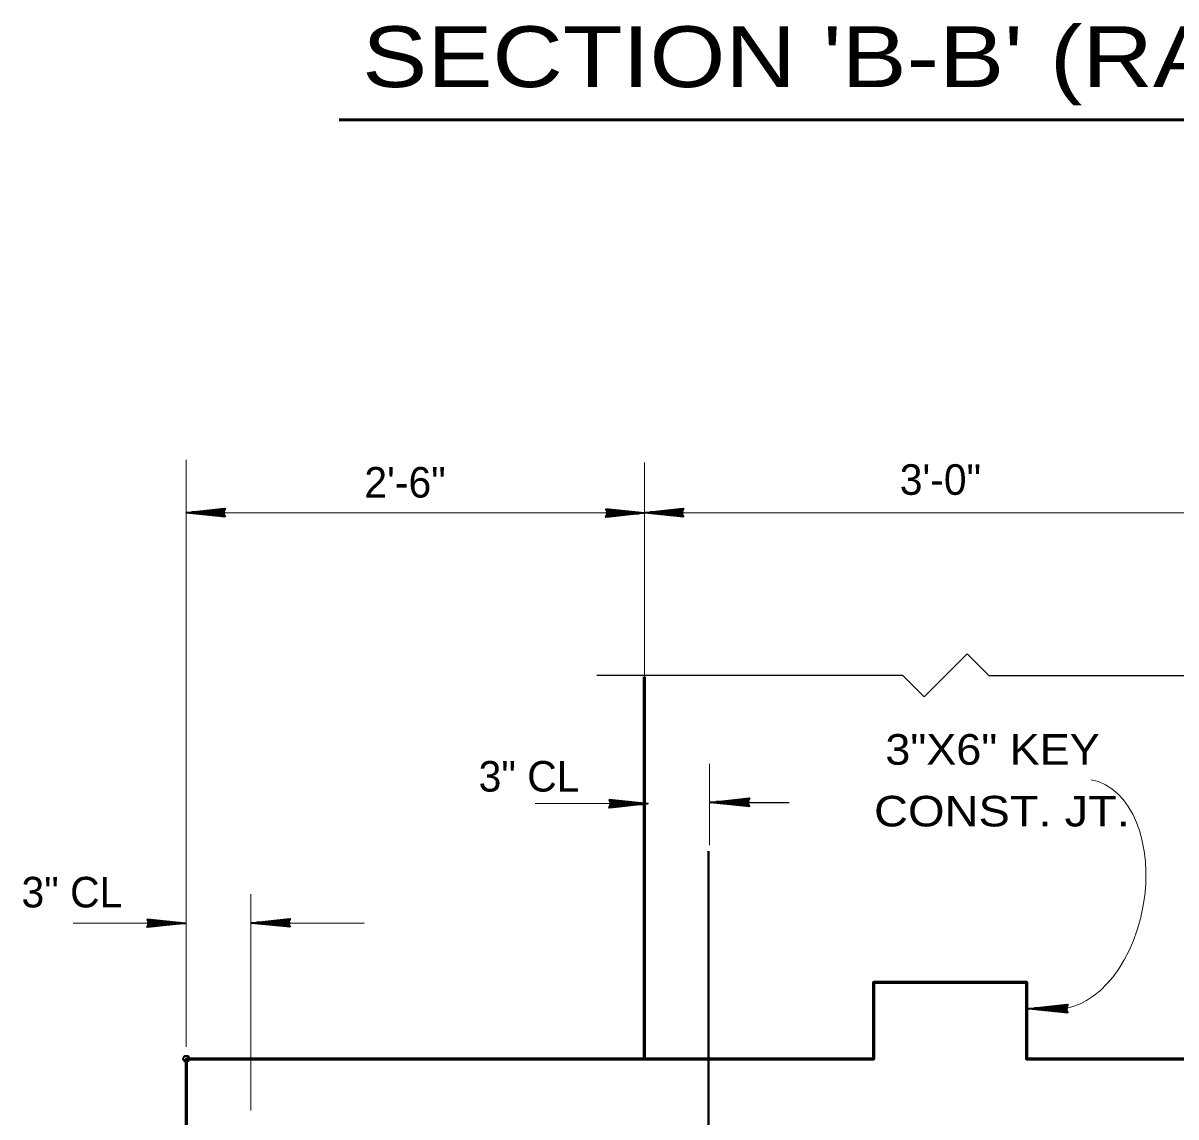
# Model space of a CAD drawing. Extents: x 4.49 to 7.69, y 0.28 to 2.27.
# Drawn here: x 5.7738 to 6.0882, y 1.4815 to 1.7797 of the extents above; entities that cross this region are included whole.
import ezdxf

# ---------------------------------------------------------------- set-up
doc = ezdxf.new("R2010")
doc.units = 0
doc.header["$LTSCALE"] = 0.0033
doc.header["$PDMODE"] = 32
doc.header["$PDSIZE"] = 0.00165
doc.layers.add('1', color=7, linetype='Continuous', lineweight=35)

msp = doc.modelspace()

# ---------------------------------------------------------------- linework, layer by layer
at = {"layer": '1', "lineweight": 53}
msp.add_line((5.86, 1.753333), (6.184583, 1.753333), dxfattribs=at)
at = {"layer": '1', "lineweight": 13}
for p, q in [((5.81825, 1.500583), (5.81825, 1.660667)), ((5.94325, 1.6015), (5.94325, 1.659917)), ((5.8185, 1.646167), (6.235167, 1.646167)), ((5.961, 1.555583), (5.961, 1.57775)), ((5.913417, 1.566917), (5.93425, 1.566917)), ((5.835917, 1.48325), (5.835917, 1.542167)), ((5.787417, 1.534333), (5.80825, 1.534333)), ((5.845917, 1.534333), (5.86675, 1.534333))]:
    msp.add_line(p, q, dxfattribs=at)
at = {"layer": '1'}
for p, q in [((5.828833, 1.646167), (5.81825, 1.646167)), ((5.828583, 1.645333), (5.82075, 1.646333)), ((5.828583, 1.645333), (5.82075, 1.646167)), ((5.828583, 1.645167), (5.82075, 1.646083)), ((5.828583, 1.645167), (5.82075, 1.646083)), ((5.828583, 1.64525), (5.82075, 1.646083)), ((5.828583, 1.64725), (5.82125, 1.646417)), ((5.828583, 1.647083), (5.82125, 1.646333)), ((5.828583, 1.647), (5.82125, 1.646167)), ((5.828667, 1.646833), (5.821333, 1.646083)), ((5.932667, 1.646167), (5.94325, 1.646167)), ((5.932833, 1.6455), (5.940167, 1.64625)), ((5.932917, 1.647167), (5.94075, 1.64625)), ((5.932917, 1.647167), (5.94075, 1.64625)), ((5.932917, 1.647083), (5.94075, 1.64625)), ((5.932917, 1.647), (5.94075, 1.646167)), ((5.932917, 1.647), (5.94075, 1.646)), ((5.932917, 1.645333), (5.94025, 1.646167)), ((5.932917, 1.64525), (5.94025, 1.646)), ((5.932917, 1.645083), (5.94025, 1.645917)), ((5.953833, 1.646167), (5.94325, 1.646167)), ((5.953583, 1.645333), (5.94575, 1.646333)), ((5.953583, 1.645333), (5.94575, 1.646167)), ((5.953583, 1.645167), (5.94575, 1.646083)), ((5.953583, 1.645167), (5.94575, 1.646083)), ((5.953583, 1.64525), (5.94575, 1.646083)), ((5.953583, 1.64725), (5.94625, 1.646417)), ((5.953583, 1.647083), (5.94625, 1.646333)), ((5.953583, 1.647), (5.94625, 1.646167)), ((5.953667, 1.646833), (5.946333, 1.646083)), ((5.933583, 1.566917), (5.944167, 1.566917)), ((5.93375, 1.56625), (5.941083, 1.567)), ((5.933833, 1.567917), (5.941667, 1.567)), ((5.933833, 1.567917), (5.941667, 1.567)), ((5.933833, 1.567833), (5.941667, 1.567)), ((5.933833, 1.56775), (5.941667, 1.566917)), ((5.933833, 1.56775), (5.941667, 1.56675)), ((5.933833, 1.566083), (5.941167, 1.566917)), ((5.933833, 1.566), (5.941167, 1.56675)), ((5.933833, 1.565833), (5.941167, 1.566667)), ((5.971833, 1.567167), (5.96125, 1.567167)), ((5.971583, 1.566333), (5.96375, 1.567333)), ((5.971583, 1.566333), (5.96375, 1.567167)), ((5.971583, 1.566167), (5.96375, 1.567083)), ((5.971583, 1.566167), (5.96375, 1.567083)), ((5.971583, 1.56625), (5.96375, 1.567083)), ((5.971583, 1.56825), (5.96425, 1.567417)), ((5.971583, 1.568083), (5.96425, 1.567333)), ((5.971583, 1.568), (5.96425, 1.567167)), ((5.971667, 1.567833), (5.964333, 1.567083)), ((5.807583, 1.534333), (5.818167, 1.534333)), ((5.80775, 1.533667), (5.815083, 1.534417)), ((5.807833, 1.535333), (5.815667, 1.534417)), ((5.807833, 1.535333), (5.815667, 1.534417)), ((5.807833, 1.53525), (5.815667, 1.534417)), ((5.807833, 1.535167), (5.815667, 1.534333)), ((5.807833, 1.535167), (5.815667, 1.534167)), ((5.807833, 1.5335), (5.815167, 1.534333)), ((5.846583, 1.534333), (5.836, 1.534333)), ((5.846333, 1.5335), (5.8385, 1.5345)), ((5.846333, 1.5335), (5.8385, 1.534333)), ((5.846333, 1.535417), (5.839, 1.534583)), ((5.846333, 1.53525), (5.839, 1.5345)), ((5.846333, 1.535167), (5.839, 1.534333)), ((5.846417, 1.535), (5.839083, 1.53425)), ((5.807833, 1.533417), (5.815167, 1.534167)), ((5.807833, 1.53325), (5.815167, 1.534083)), ((5.846333, 1.533333), (5.8385, 1.53425)), ((5.846333, 1.533333), (5.8385, 1.53425)), ((5.846333, 1.533417), (5.8385, 1.53425)), ((6.058667, 1.510917), (6.048083, 1.510917)), ((6.058417, 1.510083), (6.050583, 1.511083)), ((6.058417, 1.510083), (6.050583, 1.510917)), ((6.058417, 1.509917), (6.050583, 1.510833)), ((6.058417, 1.509917), (6.050583, 1.510833)), ((6.058417, 1.51), (6.050583, 1.510833)), ((6.058417, 1.512), (6.051083, 1.511167)), ((6.058417, 1.511833), (6.051083, 1.511083)), ((6.058417, 1.51175), (6.051083, 1.510917)), ((6.0585, 1.511583), (6.051167, 1.510833))]:
    msp.add_line(p, q, dxfattribs=at)
at = {"layer": '1', "lineweight": 25}
msp.add_line((5.967583, 1.567167), (5.982667, 1.567167), dxfattribs=at)
at = {"layer": '1'}
for points in [[(5.828833, 1.645083), (5.81825, 1.646167), (5.828833, 1.647333), (5.82825, 1.646167)], [(5.828083, 1.646083), (5.823417, 1.646), (5.823417, 1.646083), (5.824333, 1.646083), (5.828083, 1.646), (5.825083, 1.645917), (5.82825, 1.645833), (5.826, 1.64575), (5.82825, 1.645667), (5.82475, 1.645917), (5.820083, 1.646083), (5.821, 1.646333), (5.81975, 1.646333), (5.828083, 1.646333), (5.825667, 1.6465), (5.82825, 1.6465), (5.822917, 1.646083), (5.82825, 1.64675)], [(5.932667, 1.64725), (5.94325, 1.646167), (5.932667, 1.645), (5.93325, 1.646167)], [(5.933417, 1.64625), (5.938083, 1.646333), (5.938083, 1.64625), (5.937167, 1.64625), (5.933417, 1.646333), (5.936417, 1.646417), (5.93325, 1.6465), (5.9355, 1.646583), (5.93325, 1.646667), (5.93675, 1.646417), (5.941417, 1.64625), (5.9405, 1.646), (5.94175, 1.646), (5.933417, 1.646), (5.935833, 1.645833), (5.93325, 1.645833), (5.938583, 1.64625), (5.93325, 1.645583)], [(5.953833, 1.645083), (5.94325, 1.646167), (5.953833, 1.647333), (5.95325, 1.646167)], [(5.953083, 1.646083), (5.948417, 1.646), (5.948417, 1.646083), (5.949333, 1.646083), (5.953083, 1.646), (5.950083, 1.645917), (5.95325, 1.645833), (5.951, 1.64575), (5.95325, 1.645667), (5.94975, 1.645917), (5.945083, 1.646083), (5.946, 1.646333), (5.94475, 1.646333), (5.953083, 1.646333), (5.950667, 1.6465), (5.95325, 1.6465), (5.947917, 1.646083), (5.95325, 1.64675)], [(5.933583, 1.568), (5.944167, 1.566917), (5.933583, 1.56575), (5.934167, 1.566917)], [(5.934333, 1.567), (5.939, 1.567083), (5.939, 1.567), (5.938083, 1.567), (5.934333, 1.567083), (5.937333, 1.567167), (5.934167, 1.56725), (5.936417, 1.567333), (5.934167, 1.567417), (5.937667, 1.567167), (5.942333, 1.567), (5.941417, 1.56675), (5.942667, 1.56675), (5.934333, 1.56675), (5.93675, 1.566583), (5.934167, 1.566583), (5.9395, 1.567), (5.934167, 1.566333)], [(5.971833, 1.566083), (5.96125, 1.567167), (5.971833, 1.568333), (5.97125, 1.567167)], [(5.971083, 1.567083), (5.966417, 1.567), (5.966417, 1.567083), (5.967333, 1.567083), (5.971083, 1.567), (5.968083, 1.566917), (5.97125, 1.566833), (5.969, 1.56675), (5.97125, 1.566667), (5.96775, 1.566917), (5.963083, 1.567083), (5.964, 1.567333), (5.96275, 1.567333), (5.971083, 1.567333), (5.968667, 1.5675), (5.97125, 1.5675), (5.965917, 1.567083), (5.97125, 1.56775)], [(5.807583, 1.535417), (5.818167, 1.534333), (5.807583, 1.533167), (5.808167, 1.534333)], [(5.808333, 1.534417), (5.813, 1.5345), (5.813, 1.534417), (5.812083, 1.534417), (5.808333, 1.5345), (5.811333, 1.534583), (5.808167, 1.534667), (5.810417, 1.53475), (5.808167, 1.534833), (5.811667, 1.534583), (5.816333, 1.534417), (5.815417, 1.534167), (5.816667, 1.534167), (5.808333, 1.534167), (5.81075, 1.534), (5.808167, 1.534), (5.8135, 1.534417), (5.808167, 1.53375)], [(5.846583, 1.53325), (5.836, 1.534333), (5.846583, 1.5355), (5.846, 1.534333)], [(5.845833, 1.53425), (5.841167, 1.534167), (5.841167, 1.53425), (5.842083, 1.53425), (5.845833, 1.534167), (5.842833, 1.534083), (5.846, 1.534), (5.84375, 1.533917), (5.846, 1.533833), (5.8425, 1.534083), (5.837833, 1.53425), (5.83875, 1.5345), (5.8375, 1.5345), (5.845833, 1.5345), (5.843417, 1.534667), (5.846, 1.534667), (5.840667, 1.53425), (5.846, 1.534917)], [(6.058667, 1.509833), (6.048083, 1.510917), (6.058667, 1.512083), (6.058083, 1.510917)], [(6.057917, 1.510833), (6.05325, 1.51075), (6.05325, 1.510833), (6.054167, 1.510833), (6.057917, 1.51075), (6.054917, 1.510667), (6.058083, 1.510583), (6.055833, 1.5105), (6.058083, 1.510417), (6.054583, 1.510667), (6.049917, 1.510833), (6.050833, 1.511083), (6.049583, 1.511083), (6.057917, 1.511083), (6.0555, 1.51125), (6.058083, 1.51125), (6.05275, 1.510833), (6.058083, 1.5115)]]:
    msp.add_lwpolyline(points, close=True, dxfattribs=at)
for points in [[(5.828083, 1.646083), (5.8285, 1.645333), (5.82825, 1.645583), (5.828083, 1.645917), (5.827833, 1.645833), (5.828, 1.6455), (5.828167, 1.64625), (5.828333, 1.64675), (5.828583, 1.647167)], [(5.933417, 1.64625), (5.933, 1.647), (5.93325, 1.64675), (5.933417, 1.646417), (5.933667, 1.6465), (5.9335, 1.646833), (5.933333, 1.646083), (5.933167, 1.645583), (5.932917, 1.645167)], [(5.953083, 1.646083), (5.9535, 1.645333), (5.95325, 1.645583), (5.953083, 1.645917), (5.952833, 1.645833), (5.953, 1.6455), (5.953167, 1.64625), (5.953333, 1.64675), (5.953583, 1.647167)], [(5.934333, 1.567), (5.933917, 1.56775), (5.934167, 1.5675), (5.934333, 1.567167), (5.934583, 1.56725), (5.934417, 1.567583), (5.93425, 1.566833), (5.934083, 1.566333), (5.933833, 1.565917)], [(5.971083, 1.567083), (5.9715, 1.566333), (5.97125, 1.566583), (5.971083, 1.566917), (5.970833, 1.566833), (5.971, 1.5665), (5.971167, 1.56725), (5.971333, 1.56775), (5.971583, 1.568167)], [(5.808333, 1.534417), (5.807917, 1.535167), (5.808167, 1.534917), (5.808333, 1.534583), (5.808583, 1.534667), (5.808417, 1.535), (5.80825, 1.53425), (5.808083, 1.53375), (5.807833, 1.533333)], [(5.845833, 1.53425), (5.84625, 1.5335), (5.846, 1.53375), (5.845833, 1.534083), (5.845583, 1.534), (5.84575, 1.533667), (5.845917, 1.534417), (5.846083, 1.534917), (5.846333, 1.535333)], [(6.057917, 1.510833), (6.058333, 1.510083), (6.058083, 1.510333), (6.057917, 1.510667), (6.057667, 1.510583), (6.057833, 1.51025), (6.058, 1.511), (6.058167, 1.5115), (6.058417, 1.511917)]]:
    msp.add_lwpolyline(points, dxfattribs=at)
at = {"layer": '1', "lineweight": 25}
msp.add_lwpolyline([(5.93025, 1.601917), (6.013583, 1.601917), (6.0195, 1.596), (6.03125, 1.60775), (6.037167, 1.601833), (6.1205, 1.601833)], dxfattribs=at)
at = {"layer": '1', "lineweight": 60}
for points in [[(5.81825, 1.497333), (5.94325, 1.497333), (5.94325, 1.6015)], [(5.94325, 1.497333), (6.00575, 1.497333), (6.00575, 1.518167), (6.047417, 1.518167), (6.047417, 1.497333), (6.109917, 1.497333)], [(5.81825, 1.497333), (5.81825, 1.414), (6.234917, 1.414), (6.234917, 1.497333)]]:
    msp.add_lwpolyline(points, dxfattribs=at)
at = {"layer": '1', "lineweight": 40}
msp.add_lwpolyline([(5.898167, 1.44175), (5.960667, 1.44175), (5.960667, 1.553917)], dxfattribs=at)
at = {"layer": '1', "lineweight": 13}
msp.add_ellipse((6.059375, 1.542292), major_axis=(0.005708, 0.031125), ratio=0.635583, start_param=3.1415927, end_param=6.2831853, dxfattribs=at)
at = {"layer": '1'}
msp.add_point((5.81825, 1.497333), dxfattribs=at)

# ---------------------------------------------------------------- texts
for s, height, width, p in [("SECTION 'B-B' (RANGE I)", 0.01658, 1.2, (5.86625, 1.76225)), ('3"X6" KEY', 0.008334, 1.1, (6.008917, 1.5775)), ('CONST. JT. ', 0.008334, 1.15, (6.005833, 1.560667))]:
    msp.add_text(s, height=height, dxfattribs=dict(at, width=width)).set_placement(p)
for s, height, p in [('2\'-6"', 0.008333, (5.866833, 1.650333)), ('3\'-0"', 0.008333, (6.012833, 1.651083)), ('3" CL', 0.008334, (5.898, 1.570167)), ('3" CL', 0.008334, (5.773333, 1.538583))]:
    msp.add_text(s, height=height, dxfattribs=at).set_placement(p)

doc.saveas('drawing.dxf')
